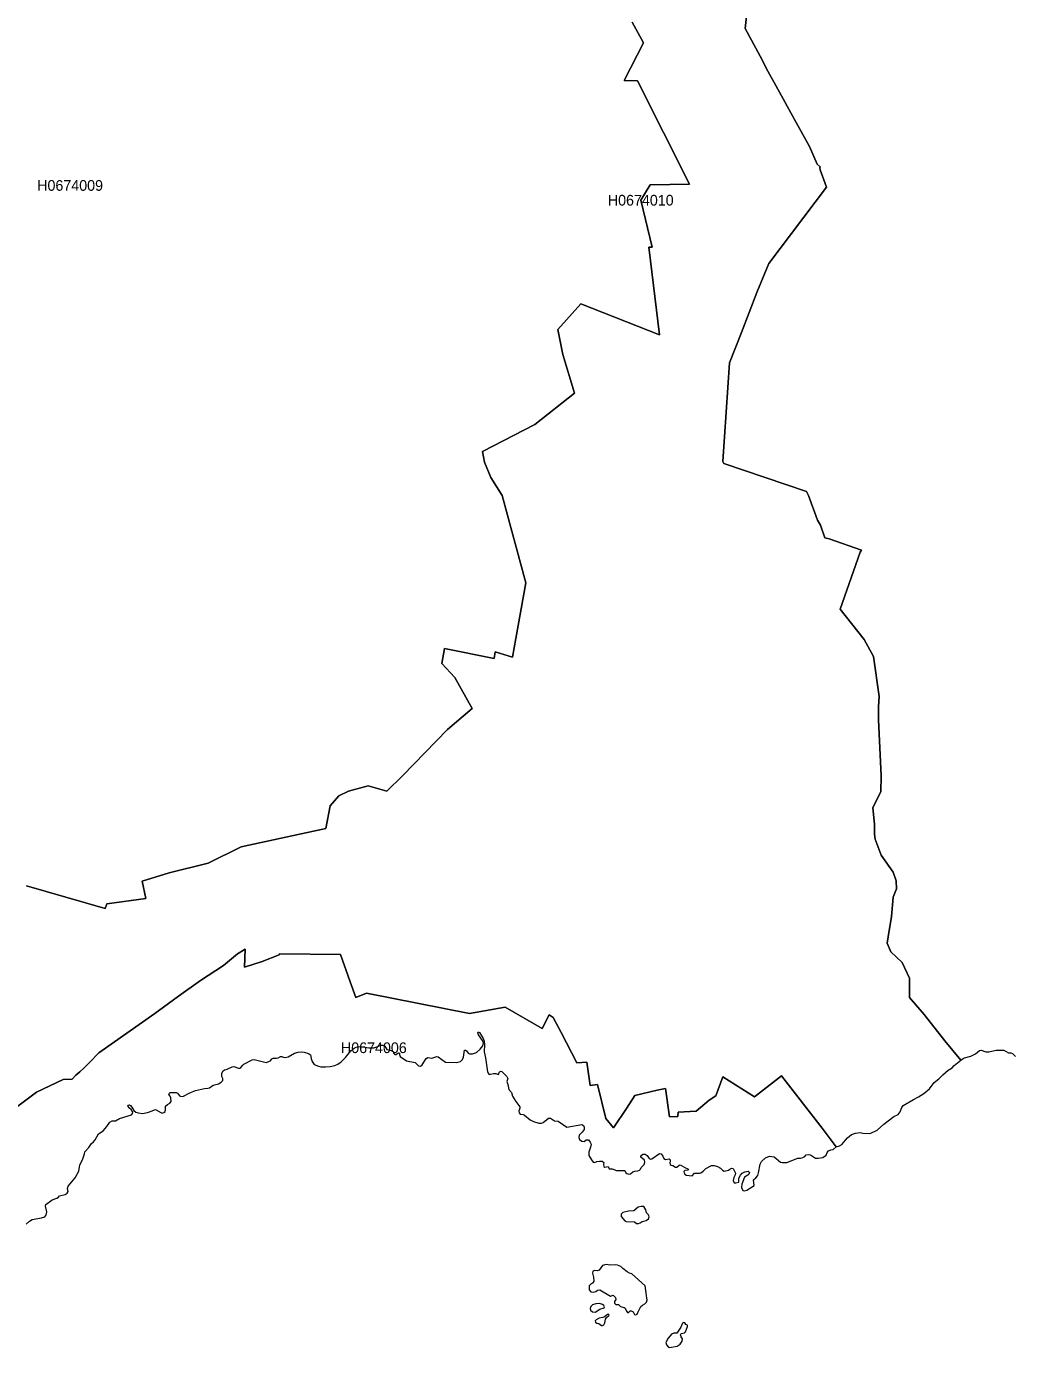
# Model space of a CAD drawing. Extents: x 369010 to 739155, y 6377141 to 6616555.
# Drawn here: x 474982 to 484230, y 6513819 to 6526211 of the extents above; entities that cross this region are included whole.
import ezdxf
from ezdxf.enums import TextEntityAlignment as Align

# ---------------------------------------------------------------- set-up
doc = ezdxf.new("R2010")
doc.units = 0
doc.header["$LTSCALE"] = 40
doc.layers.add('1', color=7, linetype='Continuous', lineweight=13)
doc.layers.add('2', color=7, linetype='Continuous')

msp = doc.modelspace()

# ---------------------------------------------------------------- linework, layer by layer
at = {"layer": '1'}
for points in [[(481764.6, 6526562.96), (481722.24, 6526190.41), (481861.75, 6525932.72), (481936.4, 6525791.22), (482011.21, 6525656.33), (482183.83, 6525337.9), (482326.99, 6525086.34), (482396.83, 6524919.01), (482424.63, 6524893.69), (482422.15, 6524883.76), (482425.79, 6524867.04), (482485.37, 6524702.03), (481943.18, 6523988.55), (481832.79, 6523716.62), (481687.98, 6523339.77), (481574.11, 6523054.44), (481511.88, 6522129.61), (481521.15, 6522111.07), (482296.37, 6521847.92), (482317.39, 6521810.18), (482402.13, 6521580.3), (482428.77, 6521533.13), (482469.65, 6521415.79), (482510.7, 6521404.86), (482812.24, 6521298.45), (482802.48, 6521280.74), (482612.15, 6520744.17), (482839.72, 6520460), (482924.95, 6520301.61), (482979.07, 6519925.75), (482971.79, 6519829.76), (482972.62, 6519705.8), (482998.6, 6519183.3), (482994.63, 6519032.86), (482920.65, 6518884.9), (482935.71, 6518724.86), (482936.21, 6518634.33), (482941.83, 6518586.66), (482997.94, 6518437.05), (483109.16, 6518277.5), (483138.62, 6518198.06), (483142.76, 6518121.6), (483110.98, 6518043.97), (483094.59, 6517861.92), (483063.65, 6517672.42), (483054.54, 6517610.69), (483089.63, 6517530.58), (483196.05, 6517431.61), (483262.58, 6517285.47), (483263.24, 6517103.42), (483400.45, 6516942.05), (483595.57, 6516697.6), (483746.35, 6516513.39), (483766.71, 6516530.77), (483780.61, 6516537.72), (483840.19, 6516551.62), (483882.89, 6516574.13), (483921.12, 6516605.25), (483936.18, 6516608.23), (483980.7, 6516594.33), (484007.85, 6516592.01), (484076.03, 6516609.88), (484148.85, 6516609.88), (484193.21, 6516584.56), (484213.57, 6516582.74), (484230.28, 6516576.45), (484257.92, 6516550.47)], [(482064.33, 6516366.59), (482444.99, 6515877.2), (482575.9, 6515701.93), (482607.18, 6515711.2), (482629.2, 6515724.93), (482681.17, 6515786.83), (482718.73, 6515818.11), (482756.3, 6515831.35), (482799.67, 6515836.48), (482824.99, 6515831.35), (482887.38, 6515826.06), (482902.44, 6515829.37), (482959.71, 6515858), (483022.6, 6515913.94), (483115.78, 6515986.76), (483156.16, 6516006.62), (483175.36, 6516029.46), (483191.25, 6516070.01), (483205.32, 6516088.54), (483301.81, 6516145.64), (483349.47, 6516170.14), (483396.8, 6516203.07), (483451.75, 6516246.44), (483493.96, 6516304.2), (483537.81, 6516338.29), (483576.05, 6516378.18), (483626.19, 6516420.38), (483664.92, 6516444.05), (483684.12, 6516464.24), (483746.35, 6516513.39), (483595.57, 6516697.6), (483400.45, 6516942.05), (483263.24, 6517103.42), (483262.58, 6517285.47), (483196.05, 6517431.61), (483089.63, 6517530.58), (483054.54, 6517610.69), (483063.65, 6517672.42), (483094.59, 6517861.92), (483110.98, 6518043.97), (483142.76, 6518121.6), (483138.62, 6518198.06), (483109.16, 6518277.5), (482997.94, 6518437.05), (482941.83, 6518586.66), (482936.21, 6518634.33), (482935.71, 6518724.86), (482920.65, 6518884.9), (482994.63, 6519032.86), (482998.6, 6519183.3), (482972.62, 6519705.8), (482971.79, 6519829.76), (482979.07, 6519925.75), (482924.95, 6520301.61), (482839.72, 6520460), (482612.15, 6520744.17), (482802.48, 6521280.74), (482812.24, 6521298.45), (482510.7, 6521404.86), (482469.65, 6521415.79), (482428.77, 6521533.13), (482402.13, 6521580.3), (482317.39, 6521810.18), (482296.37, 6521847.92), (481521.15, 6522111.07), (481511.88, 6522129.61), (481574.11, 6523054.44), (481687.98, 6523339.77), (481832.79, 6523716.62), (481943.18, 6523988.55), (482485.37, 6524702.03), (482425.79, 6524867.04), (482422.15, 6524883.76), (482424.63, 6524893.69), (482396.83, 6524919.01), (482326.99, 6525086.34), (482183.83, 6525337.9), (482011.21, 6525656.33), (481936.4, 6525791.22), (481861.75, 6525932.72), (481722.24, 6526190.41), (481764.6, 6526562.96)], [(474981.42, 6518150.72), (475721.56, 6517937.06), (475735.13, 6517981.41), (476100.23, 6518031.4), (476067.29, 6518195.25), (476320.35, 6518272.37), (476685.29, 6518363.23), (476996.43, 6518516.65), (477788.37, 6518688.61), (477829.75, 6518900.79), (477912.83, 6518993.47), (478001.54, 6519038.49), (478187.24, 6519088.3), (478361.01, 6519038.82), (478508.15, 6519181.81), (478929.85, 6519616.26), (479163.54, 6519813.38), (478998.54, 6520102.84), (478877.39, 6520234.09), (478903.04, 6520376.26), (479368.44, 6520280.93), (479379.36, 6520343.98), (479541.39, 6520295.99), (479570.35, 6520469.93), (479664.69, 6520992.59), (479444.57, 6521812.67), (479336.33, 6521981.31), (479279.23, 6522123.15), (479259.87, 6522223.94), (479750.75, 6522477.33), (480121.48, 6522772.59), (480011.75, 6523135.37), (479964.58, 6523367.25), (480181.89, 6523610.04), (480917.55, 6523318.92), (480817.92, 6524139.49), (480850.53, 6524139.49), (480743.11, 6524581.05), (480831.99, 6524724.71), (481200.24, 6524731.99), (480711.67, 6525702.34), (480586.38, 6525703.66), (480768.44, 6526058.84), (480663.51, 6526252.48)], [(480663.51, 6526252.48), (480768.44, 6526058.84), (480586.38, 6525703.66), (480711.67, 6525702.34), (481200.24, 6524731.99), (480831.99, 6524724.71), (480743.11, 6524581.05), (480850.53, 6524139.49), (480817.92, 6524139.49), (480917.55, 6523318.92), (480181.89, 6523610.04), (479964.58, 6523367.25), (480011.75, 6523135.37), (480121.48, 6522772.59), (479750.75, 6522477.33), (479259.87, 6522223.94), (479279.23, 6522123.15), (479336.33, 6521981.31)], [(479336.33, 6521981.31), (479444.57, 6521812.67), (479664.69, 6520992.59), (479570.35, 6520469.93), (479541.39, 6520295.99), (479379.36, 6520343.98), (479368.44, 6520280.93), (478903.04, 6520376.26), (478877.39, 6520234.09), (478998.54, 6520102.84), (479163.54, 6519813.38), (478929.85, 6519616.26), (478508.15, 6519181.81), (478361.01, 6519038.82), (478187.24, 6519088.3), (478001.54, 6519038.49), (477912.83, 6518993.47), (477829.75, 6518900.79), (477788.37, 6518688.61), (476996.43, 6518516.65), (476685.29, 6518363.23), (476320.35, 6518272.37), (476067.29, 6518195.25), (476100.23, 6518031.4), (475735.13, 6517981.41), (475721.56, 6517937.06), (474981.42, 6518150.72)], [(474800.2, 6516008.94), (475075.76, 6516215.98), (475327.16, 6516332), (475409.25, 6516336.64), (475446.32, 6516373.38), (475483.89, 6516405.32), (475521.3, 6516440.74), (475569.79, 6516489.89), (475661.98, 6516584.73), (475924.46, 6516767.11), (476186.95, 6516952.81), (476268.22, 6517011.89), (476407.24, 6517113.51), (476614.29, 6517261.14), (476829.77, 6517402.65), (476961.35, 6517511.55), (477033.18, 6517555.74), (477028.05, 6517385.77), (477193.38, 6517440.22), (477352.43, 6517503.6), (477354.92, 6517512.21), (477927.23, 6517506.75), (478016.93, 6517250.88), (478070.55, 6517103.08), (478170.35, 6517143.8), (479138.06, 6516952.97), (479471.05, 6517012.06), (479817.95, 6516812.79), (479882.82, 6516939.73), (479923.37, 6516916.06), (479995.86, 6516774.72), (480143.66, 6516489.4), (480237.66, 6516494.86), (480267.62, 6516277.72), (480338.13, 6516285.66), (480416.57, 6515967.73), (480489.06, 6515879.35), (480609.72, 6516061.07), (480687.84, 6516183.05), (480896.04, 6516232.2), (480976.64, 6516250.08), (481014.21, 6515982.13), (481092.49, 6515985.1), (481095.31, 6516026.81), (481261.8, 6516036.58), (481383.61, 6516139.85), (481446.84, 6516181.72), (481512.05, 6516359.47), (481811.11, 6516171.3), (482064.33, 6516366.59)], [(479471.05, 6517012.06), (479138.06, 6516952.97), (478170.35, 6517143.8), (478070.55, 6517103.08), (478016.93, 6517250.88), (477927.23, 6517506.75), (477354.92, 6517512.21), (477352.43, 6517503.6), (477193.38, 6517440.22), (477028.05, 6517385.77), (477033.18, 6517555.74), (476961.35, 6517511.55), (476829.77, 6517402.65), (476614.29, 6517261.14), (476407.24, 6517113.51), (476268.22, 6517011.89), (476186.95, 6516952.81), (475924.46, 6516767.11), (475661.98, 6516584.73), (475569.79, 6516489.89), (475521.3, 6516440.74), (475483.89, 6516405.32), (475446.32, 6516373.38), (475409.25, 6516336.64), (475327.16, 6516332), (475075.76, 6516215.98)], [(481191.13, 6515488.92), (481187, 6515481.48), (481156.38, 6515479.16), (481147.27, 6515469.89), (481149.59, 6515456.65), (481155.22, 6515446.22), (481170.28, 6515434.64), (481224.07, 6515429.51), (481246.58, 6515455.49), (481292.75, 6515455), (481307.81, 6515459.46), (481329.83, 6515473.37), (481353.49, 6515497.03), (481406.12, 6515527.16), (481432.6, 6515525.33), (481462.06, 6515516.73), (481490.53, 6515502.33), (481510.72, 6515482.63), (481526.94, 6515474.52), (481565.17, 6515482.63), (481578.25, 6515493.72), (481597.94, 6515501.83), (481610.69, 6515497.36), (481630.38, 6515454), (481628.89, 6515437.95), (481616.64, 6515413.79), (481610.19, 6515384.99), (481620.62, 6515364.8), (481635.01, 6515362.98), (481661.66, 6515369.93), (481663.98, 6515409.32), (481677.22, 6515434.64), (481694.1, 6515453.84), (481720.08, 6515467.57), (481749.54, 6515472.21), (481762.78, 6515462.44), (481756.49, 6515446.22), (481747.23, 6515436.46), (481717.77, 6515416.76), (481692.28, 6515350.89), (481688.8, 6515319.61), (481700.89, 6515293.13), (481714.79, 6515288.5), (481739.61, 6515294.29), (481806.64, 6515339.31), (481799.19, 6515393.1), (481821.7, 6515412.13), (481840.24, 6515433.48), (481847.69, 6515457.15), (481862.25, 6515538.08), (481877.15, 6515565.22), (481914.22, 6515598.82), (481949.47, 6515612.72), (481993.33, 6515606.93), (482054.57, 6515558.27), (482071.45, 6515554.79), (482111.83, 6515554.79), (482123.91, 6515557.11), (482145.93, 6515568.7), (482216.43, 6515595.34), (482241.92, 6515595.34), (482264.43, 6515600.47), (482281.14, 6515611.56), (482296.2, 6515628.28), (482314.74, 6515631.09), (482336.09, 6515625.3), (482381.11, 6515595.84), (482406.59, 6515595.34), (482451.61, 6515602.29), (482482.23, 6515622.98), (482492.66, 6515648.47), (482505.4, 6515664.69), (482525.1, 6515673.63), (482546.45, 6515675.94), (482575.9, 6515701.93), (482444.99, 6515877.2), (482064.33, 6516366.59), (481811.11, 6516171.3), (481512.05, 6516359.47), (481446.84, 6516181.72), (481383.61, 6516139.85), (481261.8, 6516036.58), (481095.31, 6516026.81), (481092.49, 6515985.1), (481014.21, 6515982.13), (480976.64, 6516250.08), (480896.04, 6516232.2), (480687.84, 6516183.05), (480609.72, 6516061.07), (480489.06, 6515879.35), (480416.57, 6515967.73), (480338.13, 6516285.66), (480267.62, 6516277.72), (480237.66, 6516494.86), (480143.66, 6516489.4), (479995.86, 6516774.72), (479923.37, 6516916.06), (479882.82, 6516939.73), (479817.95, 6516812.79), (479471.05, 6517012.06)], [(476910.04, 6516451.66), (476927.25, 6516455.14), (476971.11, 6516440.9), (476982.86, 6516440.9), (476992.3, 6516444.71), (477010.01, 6516468.87), (477019.77, 6516477.31), (477097.56, 6516518.19), (477117.75, 6516522.5), (477229.46, 6516493.04), (477270.84, 6516509.75), (477282.09, 6516526.96), (477296.99, 6516533.92), (477325.95, 6516532.92), (477343.16, 6516537.39), (477363.36, 6516548.15), (477375.6, 6516548.65), (477390, 6516542.69), (477409.7, 6516540.7), (477436.67, 6516545.67), (477495.26, 6516579.1), (477530.68, 6516590.02), (477558.32, 6516592.5), (477586.79, 6516590.52), (477626.18, 6516578.11), (477644.38, 6516565.86), (477650.84, 6516530.44), (477661.59, 6516502.8), (477681.29, 6516475.33), (477721.18, 6516457.12), (477743.85, 6516451.16), (477787.21, 6516450.67), (477829.42, 6516454.64), (477874.27, 6516465.4), (477900.91, 6516476.32), (477932.36, 6516500.32), (477974.73, 6516540.7), (478025.37, 6516602.77), (478055.33, 6516625.94), (478073.7, 6516635.7), (478096.21, 6516642.16), (478158.27, 6516637.69), (478192.7, 6516631.89), (478240.03, 6516631.4), (478278.76, 6516642.82), (478305.41, 6516656.72), (478327.91, 6516655.06), (478342.97, 6516644.64), (478363.17, 6516616.34), (478404.71, 6516604.75), (478419.77, 6516596.64), (478424.4, 6516581.58), (478435.33, 6516568.84), (478445.75, 6516567.68), (478472.4, 6516585.06), (478479.85, 6516581.08), (478480.67, 6516566.52), (478488.29, 6516549.14), (478544.89, 6516508.1), (478626.98, 6516494.2), (478659.25, 6516460.76), (478677.29, 6516458.94), (478693.35, 6516470.03), (478730.92, 6516531.27), (478744.82, 6516538.22), (478785.2, 6516532.43), (478830.38, 6516549.8), (478844.78, 6516546.33), (478910.65, 6516497.17), (479014.59, 6516493.7), (479051.66, 6516502.97), (479070.7, 6516519.68), (479081.12, 6516542.19), (479089.73, 6516608.72), (479099.49, 6516609.22), (479108.26, 6516602.27), (479123.16, 6516580.42), (479137.06, 6516574.63), (479163.71, 6516573.47), (479204.09, 6516587.37), (479237.69, 6516616.83), (479263.67, 6516649.11), (479268.8, 6516678.07), (479258.54, 6516698.76), (479222.13, 6516752.05), (479215.18, 6516770.42), (479219.15, 6516779.19), (479229.58, 6516773.9), (479265.33, 6516716.8), (479275.26, 6516692.47), (479277.58, 6516662.51), (479275.76, 6516592.5), (479287.34, 6516535.9), (479306.37, 6516404.66), (479319.12, 6516384.96), (479335.34, 6516383.8), (479362.98, 6516389.6), (479384.49, 6516389.43), (479408.82, 6516381.82), (479418.58, 6516405.48)], [(474978.94, 6514977.35), (475011.38, 6515004.99), (475036.04, 6515018.73), (475122.6, 6515035.94), (475153.22, 6515046.7), (475162.48, 6515059.11), (475169.93, 6515077.32), (475172.91, 6515093.53), (475160, 6515146.66), (475164.97, 6515160.07), (475223.56, 6515203.26), (475266.92, 6515219.48), (475281.65, 6515229.41), (475293.4, 6515242.16), (475343.71, 6515253.58), (475363.9, 6515267.81), (475371.68, 6515281.55), (475367.71, 6515309.68), (475372.67, 6515332.85), (475439.54, 6515410.47), (475472.64, 6515474.03), (475482.4, 6515531.62), (475507.56, 6515581.28), (475525.77, 6515635.06), (475529.24, 6515653.77), (475566.15, 6515695.64), (475591.14, 6515733.54), (475610.83, 6515747.77), (475627.22, 6515765.98), (475658.17, 6515823.08), (475702.52, 6515851.05), (475735.96, 6515892.92), (475762.44, 6515934.3), (475785.61, 6515947.04), (475815.73, 6515944.23), (475854.62, 6515967.73), (475968.65, 6516003.14), (475977.09, 6516014.56), (475978.58, 6516025.82), (475964.35, 6516052.46), (475949.12, 6516064.22), (475934.23, 6516084.41), (475939.69, 6516091.85), (475948.63, 6516094.83), (475958.39, 6516089.37), (475969.65, 6516075.14), (475989.34, 6516043.03), (476008.04, 6516027.8), (476028.24, 6516020.52), (476069.12, 6516013.07), (476118.44, 6516022.84), (476145.91, 6516032.27), (476166.1, 6516043.03), (476192.75, 6516050.48), (476241.9, 6516023.34), (476256.13, 6516019.03), (476271.86, 6516023.34), (476283.77, 6516034.26), (476287.25, 6516047.5), (476287.25, 6516083.91), (476304.63, 6516100.13), (476325.81, 6516112.54), (476339.55, 6516128.27), (476337.07, 6516160.21), (476330.28, 6516175.93), (476317.87, 6516191.82), (476326.8, 6516211.02), (476386.88, 6516211.02), (476398.63, 6516204.56), (476416.84, 6516180.4), (476427.27, 6516175.93), (476447.46, 6516174.11), (476462.19, 6516179.41), (476507.37, 6516206.55), (476566.45, 6516231.21), (476651.69, 6516248.92), (476682.14, 6516250.9), (476697.86, 6516256.2), (476734.28, 6516279.87), (476784.09, 6516294.1), (476808.26, 6516309.82), (476823.48, 6516324.22), (476823.98, 6516341.93), (476815.54, 6516362.12), (476815.04, 6516389.6), (476823.98, 6516410.28), (476840.2, 6516425.01), (476862.87, 6516430.48), (476910.04, 6516451.66)], [(479418.58, 6516405.48), (479427.36, 6516411.94), (479440.6, 6516408.46), (479485.78, 6516362.78), (479497.2, 6516342.59), (479486.77, 6516313.13), (479497.86, 6516285.99), (479506.47, 6516239.15), (479530.8, 6516210.85), (479541.22, 6516177.25), (479572.34, 6516126.94), (479609.41, 6516078.45), (479608.25, 6516064.05), (479598.32, 6516037.4), (479601.8, 6516019.53), (479612.89, 6516009.76), (479640.03, 6516005.63), (479654.43, 6515998.68), (479704.74, 6515955.31), (479736.52, 6515938.6), (479786.17, 6515922.38), (479813.31, 6515923.54), (479827.21, 6515930.49), (479878.02, 6515969.88), (479895.4, 6515972.2), (479932.97, 6515944.39), (479967.73, 6515941.91), (480048.49, 6515886.96), (480189.5, 6515910.63), (480205.23, 6515902.02), (480213.83, 6515886.46), (480212.18, 6515865.61), (480194.14, 6515840.12), (480165.84, 6515810.17), (480163.52, 6515788.16), (480169.97, 6515769.12), (480189.5, 6515754.06), (480213.34, 6515752.9), (480232.37, 6515768.46), (480252.56, 6515766.81), (480268.78, 6515746.61), (480277.39, 6515726.26), (480273.41, 6515699.78), (480257.69, 6515652.28), (480257.19, 6515620), (480280.36, 6515579.45), (480297.58, 6515556.45), (480309.16, 6515554.13), (480330.02, 6515563.4), (480354.84, 6515568.03), (480380.33, 6515566.88), (480395.89, 6515554.63), (480393.57, 6515535.1), (480397.04, 6515518.22), (480405.65, 6515512.43), (480436.27, 6515517.72), (480447.36, 6515494.05), (480475.66, 6515495.87), (480514.88, 6515480.98), (480594.16, 6515480.32), (480603.43, 6515459.46), (480611.54, 6515450.86), (480632.89, 6515446.22), (480647.29, 6515449.7), (480667.48, 6515465.92), (480687.17, 6515472.87), (480716.14, 6515476.35), (480731.69, 6515482.63), (480741.46, 6515493.56), (480746.09, 6515507.46), (480775.55, 6515536.92), (480782.5, 6515557.28), (480777.37, 6515577.96), (480743.78, 6515605.11), (480743.78, 6515617.35), (480761.65, 6515633.41), (480784.32, 6515632.25), (480802.2, 6515619.67), (480822.39, 6515591.87), (480835.63, 6515586.07), (480847.22, 6515588.39), (480919.54, 6515639.86), (480933.94, 6515636.39), (480950.16, 6515613.88), (480959.43, 6515591.87), (480973.83, 6515582.1), (481010.24, 6515587.9), (481017.68, 6515578.63), (481019.51, 6515567.04), (481014.87, 6515550.82), (481018.84, 6515536.92), (481028.77, 6515529.97), (481044.83, 6515525.33), (481069.82, 6515510.94), (481081.9, 6515512.09), (481102.75, 6515530.63), (481112.52, 6515531.79), (481155.88, 6515506.96), (481186, 6515496.54), (481191.13, 6515488.92)], [(475075.76, 6516215.98), (474800.2, 6516008.94)]]:
    msp.add_lwpolyline(points, dxfattribs=at)
for points in [[(480782.67, 6515127.79), (480771.25, 6515141.03), (480747.75, 6515143.35), (480717.63, 6515135.9), (480679.56, 6515101.81), (480627.59, 6515098.33), (480573.97, 6515086.25), (480560.73, 6515069.54), (480560.23, 6515047.69), (480592.5, 6515008.3), (480606.9, 6515002.67), (480684.19, 6514999.2), (480704.39, 6514984.14), (480720.6, 6514981.82), (480738.48, 6514987.61), (480757.51, 6515000.36), (480793.26, 6515011.78), (480814.61, 6515025.68), (480821.56, 6515045.87), (480815.11, 6515062.59), (480798.39, 6515082.78), (480790.94, 6515112.24)], [(480525.64, 6514591.23), (480503.46, 6514595.2), (480455.96, 6514593.22), (480418.89, 6514599.01), (480384.63, 6514589.41), (480354.18, 6514545.72), (480335.15, 6514538.1), (480311.31, 6514541.91), (480294.27, 6514537.11), (480290.46, 6514517.08), (480299.07, 6514479.02), (480301.88, 6514441.95), (480292.28, 6514422.09), (480277.05, 6514416.29), (480260.01, 6514398.25), (480258.02, 6514361.18), (480275.23, 6514342.15), (480299.07, 6514339.17), (480323.4, 6514346.12), (480338.62, 6514357.54), (480358.65, 6514361.35), (480458.45, 6514301.43), (480486.09, 6514309.05), (480505.12, 6514289.02), (480509.92, 6514270.98), (480495.52, 6514250.95), (480496.51, 6514233.91), (480510.75, 6514221.49), (480533.59, 6514222.49), (480552.62, 6514205.27), (480587.87, 6514195.84), (480598.3, 6514187.23), (480609.72, 6514161.58), (480621.14, 6514145.36), (480630.57, 6514150.16), (480642.98, 6514164.4), (480653.41, 6514164.4), (480670.62, 6514152.98), (480683.86, 6514129.14), (480698.26, 6514124.51), (480710.51, 6514132.95), (480715.31, 6514149.17), (480742.95, 6514205.27), (480758.17, 6514217.69), (480780.85, 6514230.1), (480797.07, 6514246.15), (480803.85, 6514266.68), (480799.05, 6514283.72), (480795.25, 6514333.21), (480783.83, 6514398.91), (480660.2, 6514510.13), (480637.36, 6514515.93), (480614.52, 6514529.17), (480575.46, 6514561.6), (480557.42, 6514580.64)], [(480357.82, 6514233.41), (480321.41, 6514229.44), (480291.95, 6514218.52), (480275.56, 6514204.78), (480270.27, 6514185.91), (480271.59, 6514168.7), (480290.13, 6514152.81), (480316.61, 6514151.98), (480359.64, 6514179.29), (480400.19, 6514192.03), (480404.16, 6514200.48), (480398.04, 6514212.72), (480385.29, 6514222.49)], [(480444.38, 6514118.39), (480447.03, 6514127.32), (480438.26, 6514132.29), (480418.23, 6514120.54), (480403, 6514107.3), (480387.11, 6514099.68), (480354.34, 6514095.38), (480325.22, 6514080.32), (480317.27, 6514069.56), (480320.25, 6514057.15), (480330.51, 6514047.55), (480348.72, 6514043.74), (480374.54, 6514026.7), (480385.96, 6514025.54), (480396.55, 6514033.48), (480405.65, 6514050.69), (480413.26, 6514084.13), (480422.7, 6514100.01)], [(481183.19, 6514017.92), (481182.2, 6514029.18), (481166.31, 6514035.96), (481157.37, 6514050.53), (481148.76, 6514054), (481134.7, 6514047.55), (481119.3, 6514010.31), (481088.02, 6513961.82), (481080.25, 6513955.53), (481053.27, 6513953.71), (481031.42, 6513945.1), (481019.84, 6513928.06), (480998.82, 6513906.71), (480978.79, 6513867.65), (480983.43, 6513843.32), (481003.12, 6513822.63), (481011.73, 6513818.82), (481085.38, 6513831.73), (481111.53, 6513850.93), (481132.05, 6513880.06), (481133.87, 6513901.57), (481122.61, 6513918.62), (481115.83, 6513939.14), (481122.61, 6513951.56), (481152.74, 6513955.86), (481163.33, 6513967.94)]]:
    msp.add_lwpolyline(points, close=True, dxfattribs=at)

# ---------------------------------------------------------------- texts
at = {"layer": '2'}
for s, p in [('H0674009', (475391.28, 6524669.7)), ('H0674010', (480743.11, 6524531.05)), ('H0674006', (478240.04, 6516581.4))]:
    msp.add_text(s, height=100, dxfattribs=at).set_placement(p, align=Align.CENTER)

doc.saveas('drawing.dxf')
